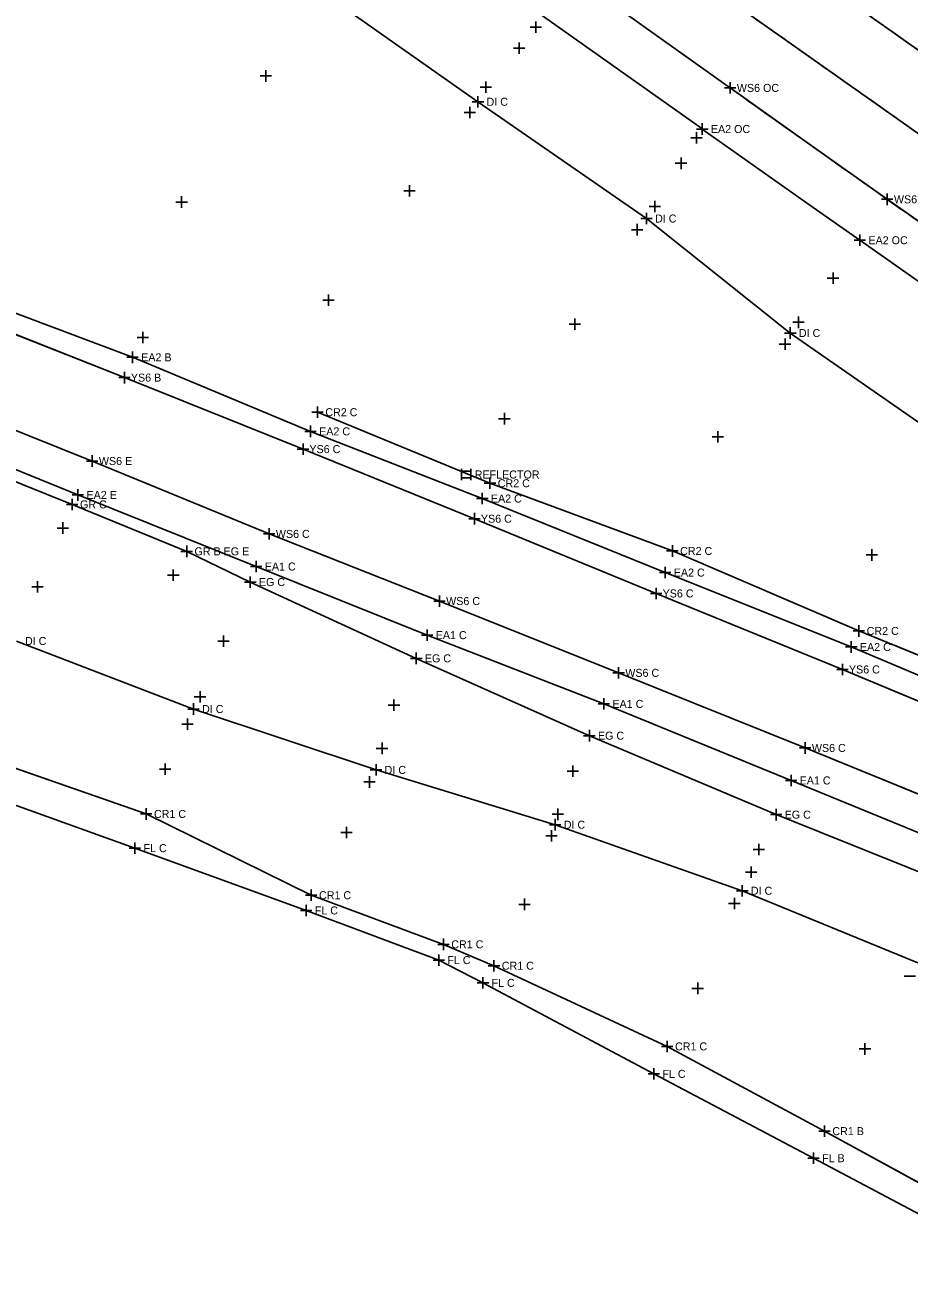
# Model space of a CAD drawing. Extents: x 1324236 to 1326110, y 459090 to 460782.
# Drawn here: x 1325184.1 to 1325338.7, y 459654.1 to 459872.5 of the extents above; entities that cross this region are included whole.
import ezdxf

# ---------------------------------------------------------------- set-up
doc = ezdxf.new("R2010")
doc.units = 0
for name, color, linetype in [('BD_X_Canopy', 7, 'Continuous'), ('DR_X_Ditch', 7, 'Continuous'), ('DR_X_Drive_Pipe', 7, 'Continuous'), ('DT_X_Island', 7, 'Continuous'), ('DT_X_Terrain_Ground_Line', 7, 'Continuous'), ('DV_X_Property_Line', 7, 'Continuous'), ('LT_X_Poles', 7, 'Continuous'), ('PM_X_CL_Double_Solid', 7, 'Continuous'), ('PM_X_Edge_Line', 7, 'Continuous'), ('PM_X_Lane_Line', 7, 'Continuous'), ('PM_X_Parking_Lot_Stall', 7, 'Continuous'), ('PV_X_Shoulder', 7, 'Continuous'), ('RW_X_CL', 7, 'Continuous'), ('RW_X_Esmt_SH', 7, 'Continuous')]:
    doc.layers.add(name, color=color, linetype=linetype)

msp = doc.modelspace()

# ---------------------------------------------------------------- linework, layer by layer
at = {"layer": 'BD_X_Canopy'}
msp.add_lwpolyline([(1325098.23, 460028.13), (1325120.97, 460011.28), (1325148.51, 459991.16), (1325175.71, 459971.23), (1325203.74, 459951.02), (1325230.1, 459931.75), (1325259.75, 459910.43), (1325314.22, 459871.98), (1325314.22, 459871.98), (1325341.7, 459852.6)], dxfattribs=at)
at = {"layer": 'DR_X_Ditch'}
for points in [[(1325105.01, 460038.08), (1325127.7, 460021.23), (1325155.6, 460000.72), (1325182.42, 459981.06), (1325210.57, 459960.69), (1325238.63, 459940.35), (1325308.7, 459890.5), (1325308.7, 459890.5), (1325349.01, 459862.04), (1325349.01, 459862.04), (1325431.77, 459803.91), (1325432.23, 459803.59), (1325432.23, 459803.59), (1325448.95, 459791.99), (1325448.95, 459791.99), (1325460.04, 459784.34), (1325460.04, 459784.34), (1325460.31, 459784.16), (1325460.31, 459784.16), (1325516.92, 459745.67), (1325550.1, 459723.2), (1325550.1, 459723.2), (1325604.67, 459686.51)], [(1325091.37, 460018.48), (1325114.18, 460001.81), (1325140.65, 459982.29), (1325168.98, 459961.47), (1325196.8, 459941.36), (1325224.07, 459921.48), (1325251.92, 459901.3), (1325270.43, 459887.92), (1325270.43, 459887.92), (1325279.78, 459881.23), (1325279.78, 459881.23), (1325307.11, 459861.77), (1325307.43, 459861.54), (1325307.43, 459861.54), (1325324.59, 459849.37), (1325324.59, 459849.37), (1325334.9, 459842.06), (1325334.9, 459842.06), (1325346.76, 459833.74)], [(1325232.73, 459798.38), (1325201.51, 459810.88), (1325169.12, 459823.7), (1325137.45, 459835.9), (1325108.1, 459847.12), (1325079.38, 459859.09), (1325074.32, 459861.12), (1325069.38, 459863.44), (1325069.38, 459863.44), (1325066.03, 459865.32), (1325062.84, 459867.47), (1325062.84, 459867.47), (1325058.04, 459871.12), (1325053.37, 459874.94)], [(1325023.99, 459854.53), (1325029.18, 459854.52), (1325034.35, 459854.01), (1325034.35, 459854.01), (1325045.33, 459852.14), (1325045.33, 459852.14), (1325050.53, 459850.91), (1325050.53, 459850.91), (1325053.41, 459850.06), (1325053.41, 459850.06), (1325072.92, 459844), (1325072.92, 459844), (1325084.48, 459840.09), (1325084.48, 459840.09), (1325102.8, 459833.11), (1325102.8, 459833.11), (1325131.65, 459821.96), (1325163.65, 459809.19), (1325195.86, 459796.3), (1325226.81, 459783.55)], [(1325358.54, 459746.7), (1325327.08, 459759.85), (1325294.49, 459773.14), (1325262.71, 459786.21), (1325232.73, 459798.38)], [(1325351.19, 459733.61), (1325320.55, 459746.12), (1325287.93, 459759.25), (1325256.59, 459771.81), (1325226.81, 459783.55)]]:
    msp.add_lwpolyline(points, dxfattribs=at)
at = {"layer": 'DR_X_Drive_Pipe'}
for p, q in [((1325263.33, 459859.12), (1325236.24, 459878.16)), ((1325292.8, 459838.7), (1325263.33, 459859.12)), ((1325317.95, 459818.68), (1325292.8, 459838.7)), ((1325346.44, 459798.83), (1325317.95, 459818.68)), ((1325213.57, 459752.93), (1325182.61, 459764.82)), ((1325245.5, 459742.28), (1325213.57, 459752.93)), ((1325276.83, 459732.7), (1325245.5, 459742.28)), ((1325309.55, 459721.15), (1325276.83, 459732.7)), ((1325340.23, 459708.56), (1325309.55, 459721.15))]:
    msp.add_line(p, q, dxfattribs=at)
at = {"layer": 'DT_X_Island'}
for p, q in [((1325265.43, 459792.41), (1325235.27, 459804.83)), ((1325297.32, 459780.57), (1325265.43, 459792.41)), ((1325329.94, 459766.58), (1325297.32, 459780.57)), ((1325361.46, 459753.73), (1325329.94, 459766.58)), ((1325205.31, 459734.58), (1325176, 459744.8)), ((1325234.17, 459720.37), (1325205.31, 459734.58)), ((1325257.3, 459711.78), (1325234.17, 459720.37)), ((1325266.13, 459708.04), (1325257.3, 459711.78)), ((1325296.43, 459693.93), (1325266.13, 459708.04)), ((1325323.94, 459679.11), (1325296.43, 459693.93)), ((1325361.32, 459658.63), (1325323.94, 459679.11))]:
    msp.add_line(p, q, dxfattribs=at)
for points in [[(1325361.46, 459753.73), (1325329.94, 459766.58), (1325297.32, 459780.57), (1325265.43, 459792.41), (1325235.27, 459804.83)], [(1325361.32, 459658.63), (1325323.94, 459679.11), (1325296.43, 459693.93), (1325266.13, 459708.04), (1325257.3, 459711.78), (1325234.17, 459720.37), (1325205.31, 459734.58), (1325176, 459744.8), (1325161.88, 459749.12), (1325145.8, 459759.39), (1325115.06, 459766.59), (1325083.29, 459777.3), (1325053.76, 459788.35), (1325045.01, 459789.31), (1325036.49, 459787.96), (1325032.69, 459782.63)], [(1325346.25, 459722.11), (1325315.46, 459734.46), (1325282.81, 459748.27), (1325252.54, 459761.79), (1325223.51, 459775.13), (1325212.39, 459780.5)]]:
    msp.add_lwpolyline(points, dxfattribs=at)
at = {"layer": 'DT_X_Terrain_Ground_Line'}
for p, q in [((1325260.47, 459794.94), (1325260.47, 459792.94)), ((1325260.47, 459794.54), (1325262.06, 459794.54)), ((1325260.47, 459793.34), (1325262.06, 459793.34)), ((1325262.06, 459794.94), (1325262.06, 459792.94))]:
    msp.add_line(p, q, dxfattribs=at)
at = {"layer": 'DV_X_Property_Line'}
for p, q in [((1325302.56, 459853.35), (1325302.56, 459855.35)), ((1325301.56, 459854.35), (1325303.56, 459854.35)), ((1325329.11, 459834.9), (1325331.11, 459834.9)), ((1325330.11, 459833.9), (1325330.11, 459835.9)), ((1325202.93, 459813.43), (1325202.93, 459815.43)), ((1325201.93, 459814.43), (1325203.93, 459814.43)), ((1325234.05, 459800.48), (1325234.05, 459802.48)), ((1325233.05, 459801.48), (1325235.05, 459801.48)), ((1325193.37, 459789.36), (1325193.37, 459791.36)), ((1325192.37, 459790.36), (1325194.37, 459790.36)), ((1325263.09, 459789.74), (1325265.09, 459789.74)), ((1325264.09, 459788.74), (1325264.09, 459790.74)), ((1325224.54, 459776.85), (1325224.54, 459778.85)), ((1325223.51, 459774.13), (1325223.51, 459776.13)), ((1325223.54, 459777.85), (1325225.54, 459777.85)), ((1325295.07, 459776.79), (1325297.07, 459776.79)), ((1325296.07, 459775.79), (1325296.07, 459777.79)), ((1325222.51, 459775.13), (1325224.51, 459775.13)), ((1325253.44, 459765.85), (1325255.44, 459765.85)), ((1325254.44, 459764.85), (1325254.44, 459766.85)), ((1325252.54, 459760.79), (1325252.54, 459762.79)), ((1325327.62, 459763.78), (1325329.62, 459763.78)), ((1325328.62, 459762.78), (1325328.62, 459764.78)), ((1325251.54, 459761.79), (1325253.54, 459761.79)), ((1325285.34, 459752.82), (1325285.34, 459754.82)), ((1325284.34, 459753.83), (1325286.34, 459753.83)), ((1325281.81, 459748.27), (1325283.81, 459748.27)), ((1325282.81, 459747.27), (1325282.81, 459749.27)), ((1325318.08, 459739.44), (1325318.08, 459741.44)), ((1325317.08, 459740.44), (1325319.08, 459740.44)), ((1325314.46, 459734.46), (1325316.46, 459734.46)), ((1325315.46, 459733.46), (1325315.46, 459735.46))]:
    msp.add_line(p, q, dxfattribs=at)
at = {"layer": 'LT_X_Poles'}
msp.add_lwpolyline([(1325105.01, 460038.08), (1325127.7, 460021.23), (1325155.6, 460000.72), (1325182.42, 459981.06), (1325210.57, 459960.69), (1325238.63, 459940.35), (1325308.7, 459890.5), (1325308.7, 459890.5), (1325349.01, 459862.04), (1325349.01, 459862.04), (1325431.77, 459803.91), (1325432.23, 459803.59), (1325432.23, 459803.59), (1325448.95, 459791.99), (1325448.95, 459791.99), (1325460.04, 459784.34), (1325460.04, 459784.34), (1325460.31, 459784.16), (1325460.31, 459784.16), (1325516.92, 459745.67), (1325550.1, 459723.2), (1325550.1, 459723.2), (1325604.67, 459686.51)], dxfattribs=at)
at = {"layer": 'PM_X_CL_Double_Solid'}
for p, q in [((1325203.34, 459728.6), (1325173.99, 459739.13)), ((1325233.29, 459717.71), (1325203.34, 459728.6)), ((1325256.47, 459709.03), (1325233.29, 459717.71)), ((1325264.2, 459705.04), (1325256.47, 459709.03)), ((1325294.08, 459689.13), (1325264.2, 459705.04)), ((1325322.01, 459674.38), (1325294.08, 459689.13)), ((1325360.24, 459654.13), (1325322.01, 459674.38))]:
    msp.add_line(p, q, dxfattribs=at)
at = {"layer": 'PM_X_Edge_Line'}
for p, q in [((1325279.78, 459881.23), (1325307.11, 459861.77)), ((1325201.51, 459810.88), (1325169.12, 459823.7)), ((1325232.73, 459798.38), (1325201.51, 459810.88)), ((1325163.65, 459809.19), (1325195.86, 459796.3)), ((1325262.71, 459786.21), (1325232.73, 459798.38)), ((1325195.86, 459796.3), (1325226.81, 459783.55)), ((1325294.49, 459773.14), (1325262.71, 459786.21)), ((1325256.59, 459771.81), (1325226.81, 459783.55)), ((1325287.93, 459759.25), (1325256.59, 459771.81)), ((1325327.08, 459759.85), (1325294.49, 459773.14)), ((1325320.55, 459746.12), (1325287.93, 459759.25)), ((1325358.54, 459746.7), (1325327.08, 459759.85)), ((1325351.19, 459733.61), (1325320.55, 459746.12))]:
    msp.add_line(p, q, dxfattribs=at)
for centre, radius, start, end in [((1331446.62, 468542.61), 10608.16, 234.647573, 234.914102), ((1325633.49, 460320.38), 562.89, 234.5621, 234.6022), ((1341812.32, 483088.04), 28493.54, 234.602178, 234.644475), ((1331280.44, 468243.86), 10292.71, 234.644475, 234.71485), ((1326291.11, 461193.3), 1655.36, 234.71485, 235.21601)]:
    msp.add_arc(centre, radius, start, end, dxfattribs=at)
at = {"layer": 'PM_X_Lane_Line'}
for centre, radius, start, end in [((1401057.98, 567206.75), 131369.22, 234.7611532, 234.7902308), ((1344588.79, 487185.54), 33429.63, 234.790231, 234.847873)]:
    msp.add_arc(centre, radius, start, end, dxfattribs=at)
at = {"layer": 'PM_X_Parking_Lot_Stall'}
for p, q in [((1325192.37, 459788.71), (1325159.73, 459801.72)), ((1325212.39, 459780.5), (1325192.37, 459788.71))]:
    msp.add_line(p, q, dxfattribs=at)
at = {"layer": 'PV_X_Shoulder'}
for points in [[(1325085.59, 460011.5), (1325108.39, 459994.82), (1325135.87, 459974.49), (1325163.8, 459954.12), (1325191.38, 459934.09), (1325219.2, 459913.96), (1325246.97, 459893.83), (1325265.48, 459880.63), (1325265.48, 459880.63), (1325274.76, 459874.04), (1325274.76, 459874.04), (1325302.45, 459854.43), (1325302.56, 459854.35), (1325302.56, 459854.35), (1325321.38, 459841.06), (1325321.38, 459841.06), (1325330.11, 459834.9), (1325330.11, 459834.9), (1325344.04, 459825.11)], [(1325234.05, 459801.48), (1325202.93, 459814.43), (1325170.18, 459826.73), (1325138.85, 459838.46), (1325108.97, 459849.32), (1325064.65, 459869.16), (1325061.08, 459871.96), (1325057.84, 459875.14), (1325054.97, 459878.66), (1325052.52, 459882.48), (1325052.52, 459882.48), (1325050.29, 459887.07), (1325048.66, 459891.9), (1325047.65, 459896.9), (1325047.65, 459896.9), (1325048.1, 459908.06), (1325059.67, 459926.39), (1325068.28, 459937.87)], [(1325022.6, 459849.51), (1325028.21, 459850.26), (1325033.85, 459850.73), (1325033.85, 459850.73), (1325036.96, 459850.67), (1325040.02, 459850.16), (1325040.02, 459850.16), (1325044.62, 459848.79), (1325049.06, 459846.99), (1325049.06, 459846.99), (1325070.63, 459838.89), (1325100.31, 459827.64), (1325129.15, 459816.15), (1325160.37, 459803.77), (1325193.37, 459790.36), (1325224.54, 459777.85)], [(1325359.98, 459750.59), (1325328.62, 459763.78), (1325296.07, 459776.79), (1325264.09, 459789.74), (1325234.05, 459801.48)], [(1325348.8, 459727.83), (1325318.08, 459740.44), (1325285.34, 459753.83), (1325254.44, 459765.85), (1325224.54, 459777.85)]]:
    msp.add_lwpolyline(points, dxfattribs=at)
at = {"layer": 'RW_X_CL'}
for p, q in [((1325272.43, 459872.15), (1325274.43, 459872.15)), ((1325273.43, 459871.15), (1325273.43, 459873.15)), ((1325269.52, 459868.49), (1325271.52, 459868.49)), ((1325270.52, 459867.49), (1325270.52, 459869.49)), ((1325225.23, 459863.63), (1325227.23, 459863.63)), ((1325226.23, 459862.63), (1325226.23, 459864.63)), ((1325263.69, 459861.66), (1325265.69, 459861.66)), ((1325264.69, 459860.66), (1325264.69, 459862.66)), ((1325306.43, 459861.54), (1325308.43, 459861.54)), ((1325307.43, 459860.54), (1325307.43, 459862.54)), ((1325260.9, 459857.23), (1325262.9, 459857.23)), ((1325261.9, 459856.23), (1325261.9, 459858.23)), ((1325300.56, 459852.82), (1325302.56, 459852.82)), ((1325301.56, 459851.82), (1325301.56, 459853.82)), ((1325297.84, 459848.36), (1325299.84, 459848.36)), ((1325298.84, 459847.36), (1325298.84, 459849.36)), ((1325250.34, 459843.54), (1325252.34, 459843.54)), ((1325251.34, 459842.54), (1325251.34, 459844.54)), ((1325210.51, 459841.59), (1325212.51, 459841.59)), ((1325211.51, 459840.59), (1325211.51, 459842.59)), ((1325294.27, 459839.81), (1325294.27, 459841.81)), ((1325333.9, 459842.06), (1325335.9, 459842.06)), ((1325334.9, 459841.06), (1325334.9, 459843.06)), ((1325293.27, 459840.81), (1325295.27, 459840.81)), ((1325291.17, 459835.75), (1325291.17, 459837.75)), ((1325290.17, 459836.75), (1325292.17, 459836.75)), ((1325324.42, 459828.28), (1325326.42, 459828.28)), ((1325325.42, 459827.28), (1325325.42, 459829.28)), ((1325236.18, 459824.41), (1325238.18, 459824.41)), ((1325237.18, 459823.41), (1325237.18, 459825.41)), ((1325279.27, 459820.22), (1325281.27, 459820.22)), ((1325280.27, 459819.22), (1325280.27, 459821.22)), ((1325318.4, 459820.55), (1325320.4, 459820.55)), ((1325319.4, 459819.55), (1325319.4, 459821.55)), ((1325203.7, 459817.91), (1325205.7, 459817.91)), ((1325204.7, 459816.91), (1325204.7, 459818.91)), ((1325317.02, 459815.74), (1325317.02, 459817.74)), ((1325316.02, 459816.74), (1325318.02, 459816.74)), ((1325200.51, 459810.88), (1325202.51, 459810.88)), ((1325201.51, 459809.88), (1325201.51, 459811.88)), ((1325234.27, 459804.83), (1325236.27, 459804.83)), ((1325235.27, 459803.83), (1325235.27, 459805.83)), ((1325267.94, 459802.7), (1325267.94, 459804.7)), ((1325266.94, 459803.7), (1325268.94, 459803.7)), ((1325304.29, 459800.51), (1325306.29, 459800.51)), ((1325305.29, 459799.51), (1325305.29, 459801.51)), ((1325231.73, 459798.38), (1325233.73, 459798.38)), ((1325232.73, 459797.38), (1325232.73, 459799.38)), ((1325194.86, 459796.3), (1325196.86, 459796.3)), ((1325195.86, 459795.3), (1325195.86, 459797.3)), ((1325265.43, 459791.41), (1325265.43, 459793.41)), ((1325264.43, 459792.41), (1325266.43, 459792.41)), ((1325262.71, 459785.21), (1325262.71, 459787.21)), ((1325189.74, 459784.58), (1325191.74, 459784.58)), ((1325190.74, 459783.58), (1325190.74, 459785.58)), ((1325226.81, 459782.55), (1325226.81, 459784.55)), ((1325261.71, 459786.21), (1325263.71, 459786.21)), ((1325225.81, 459783.55), (1325227.81, 459783.55)), ((1325296.32, 459780.57), (1325298.32, 459780.57)), ((1325297.32, 459779.57), (1325297.32, 459781.57)), ((1325332.21, 459778.87), (1325332.21, 459780.87)), ((1325331.21, 459779.87), (1325333.21, 459779.87)), ((1325209.05, 459776.35), (1325211.05, 459776.35)), ((1325210.05, 459775.35), (1325210.05, 459777.35)), ((1325185.28, 459774.29), (1325187.28, 459774.29)), ((1325186.28, 459773.29), (1325186.28, 459775.29)), ((1325294.49, 459772.14), (1325294.49, 459774.14)), ((1325255.59, 459771.81), (1325257.59, 459771.81)), ((1325256.59, 459770.81), (1325256.59, 459772.81)), ((1325293.49, 459773.14), (1325295.49, 459773.14)), ((1325329.94, 459765.58), (1325329.94, 459767.58)), ((1325218.84, 459763.79), (1325218.84, 459765.79)), ((1325328.94, 459766.58), (1325330.94, 459766.58)), ((1325217.84, 459764.79), (1325219.84, 459764.79)), ((1325327.08, 459758.85), (1325327.08, 459760.85)), ((1325286.93, 459759.25), (1325288.93, 459759.25)), ((1325287.93, 459758.25), (1325287.93, 459760.25)), ((1325326.08, 459759.85), (1325328.08, 459759.85)), ((1325214.72, 459754.08), (1325214.72, 459756.08)), ((1325213.72, 459755.08), (1325215.72, 459755.08)), ((1325248.64, 459752.6), (1325248.64, 459754.6)), ((1325247.64, 459753.6), (1325249.64, 459753.6)), ((1325211.52, 459750.29), (1325213.52, 459750.29)), ((1325212.52, 459749.29), (1325212.52, 459751.29)), ((1325245.55, 459746.05), (1325247.55, 459746.05)), ((1325246.55, 459745.05), (1325246.55, 459747.05)), ((1325319.55, 459746.12), (1325321.55, 459746.12)), ((1325320.55, 459745.12), (1325320.55, 459747.12)), ((1325208.63, 459741.43), (1325208.63, 459743.43)), ((1325279.93, 459741.05), (1325279.93, 459743.05)), ((1325207.63, 459742.43), (1325209.63, 459742.43)), ((1325244.36, 459739.17), (1325244.36, 459741.17)), ((1325278.93, 459742.05), (1325280.93, 459742.05)), ((1325243.36, 459740.17), (1325245.36, 459740.17)), ((1325204.31, 459734.58), (1325206.31, 459734.58)), ((1325205.31, 459733.58), (1325205.31, 459735.58)), ((1325276.29, 459734.52), (1325278.29, 459734.52)), ((1325277.29, 459733.52), (1325277.29, 459735.52)), ((1325240.32, 459730.32), (1325240.32, 459732.32)), ((1325239.32, 459731.32), (1325241.32, 459731.32)), ((1325275.19, 459730.74), (1325277.19, 459730.74)), ((1325276.19, 459729.74), (1325276.19, 459731.74)), ((1325311.45, 459728.35), (1325313.45, 459728.35)), ((1325312.45, 459727.35), (1325312.45, 459729.35)), ((1325310.1, 459724.41), (1325312.1, 459724.41)), ((1325311.1, 459723.41), (1325311.1, 459725.41)), ((1325234.17, 459719.37), (1325234.17, 459721.37)), ((1325233.17, 459720.37), (1325235.17, 459720.37)), ((1325271.45, 459717.78), (1325271.45, 459719.78)), ((1325308.16, 459717.92), (1325308.16, 459719.92)), ((1325270.45, 459718.77), (1325272.45, 459718.77)), ((1325307.16, 459718.92), (1325309.16, 459718.92)), ((1325257.3, 459710.78), (1325257.3, 459712.78)), ((1325256.3, 459711.78), (1325258.3, 459711.78)), ((1325265.13, 459708.04), (1325267.13, 459708.04)), ((1325266.13, 459707.04), (1325266.13, 459709.04)), ((1325337.85, 459706.19), (1325339.85, 459706.19)), ((1325300.75, 459704.08), (1325302.75, 459704.08)), ((1325301.75, 459703.08), (1325301.75, 459705.08)), ((1325296.43, 459692.93), (1325296.43, 459694.93)), ((1325295.43, 459693.93), (1325297.43, 459693.93)), ((1325330.01, 459693.48), (1325332.01, 459693.48)), ((1325331.01, 459692.48), (1325331.01, 459694.48)), ((1325323.94, 459678.11), (1325323.94, 459680.11)), ((1325322.94, 459679.11), (1325324.94, 459679.11))]:
    msp.add_line(p, q, dxfattribs=at)
at = {"layer": 'RW_X_Esmt_SH'}
for p, q in [((1325262.33, 459859.12), (1325264.33, 459859.12)), ((1325263.33, 459858.12), (1325263.33, 459860.12)), ((1325292.8, 459837.7), (1325292.8, 459839.7)), ((1325291.8, 459838.7), (1325293.8, 459838.7)), ((1325317.95, 459817.68), (1325317.95, 459819.68)), ((1325316.95, 459818.68), (1325318.95, 459818.68)), ((1325192.37, 459787.71), (1325192.37, 459789.71)), ((1325191.37, 459788.71), (1325193.37, 459788.71)), ((1325211.39, 459780.5), (1325213.39, 459780.5)), ((1325212.39, 459779.5), (1325212.39, 459781.5)), ((1325213.57, 459751.93), (1325213.57, 459753.93)), ((1325212.57, 459752.93), (1325214.57, 459752.93)), ((1325245.5, 459741.28), (1325245.5, 459743.28)), ((1325244.5, 459742.28), (1325246.5, 459742.28)), ((1325275.83, 459732.7), (1325277.83, 459732.7)), ((1325276.83, 459731.7), (1325276.83, 459733.7)), ((1325202.34, 459728.6), (1325204.34, 459728.6)), ((1325203.34, 459727.6), (1325203.34, 459729.6)), ((1325308.55, 459721.15), (1325310.55, 459721.15)), ((1325309.55, 459720.15), (1325309.55, 459722.15)), ((1325232.29, 459717.71), (1325234.29, 459717.71)), ((1325233.29, 459716.71), (1325233.29, 459718.71)), ((1325255.47, 459709.03), (1325257.47, 459709.03)), ((1325256.47, 459708.03), (1325256.47, 459710.03)), ((1325264.2, 459704.04), (1325264.2, 459706.04)), ((1325263.2, 459705.04), (1325265.2, 459705.04)), ((1325293.08, 459689.13), (1325295.08, 459689.13)), ((1325294.08, 459688.13), (1325294.08, 459690.13)), ((1325322.01, 459673.38), (1325322.01, 459675.38)), ((1325321.01, 459674.38), (1325323.01, 459674.38))]:
    msp.add_line(p, q, dxfattribs=at)

# ---------------------------------------------------------------- texts
at = {"layer": 'DV_X_Property_Line'}
for s, p in [('EA2 OC', (1325304.06, 459853.65)), ('EA2 OC', (1325331.61, 459834.2)), ('EA2 B', (1325204.43, 459813.73)), ('EA2 C', (1325235.55, 459800.78)), ('EA2 E', (1325194.87, 459789.66)), ('EA2 C', (1325265.59, 459789.04)), ('EA1 C', (1325226.04, 459777.15)), ('EG C', (1325225.01, 459774.43)), ('EA2 C', (1325297.57, 459776.09)), ('EA1 C', (1325255.94, 459765.15)), ('EA2 C', (1325330.12, 459763.08)), ('EG C', (1325254.04, 459761.09)), ('EA1 C', (1325286.84, 459753.12)), ('EG C', (1325284.31, 459747.57)), ('EA1 C', (1325319.58, 459739.74)), ('EG C', (1325316.96, 459733.76))]:
    msp.add_text(s, height=1.4, dxfattribs=at).set_placement(p)
at = {"layer": 'RW_X_CL'}
for s, p in [('WS6 OC', (1325308.6, 459860.84)), ('WS6 OC', (1325336.07, 459841.36)), ('YS6 B', (1325202.63, 459810.18)), ('CR2 C', (1325236.63, 459804.13)), ('YS6 C', (1325233.85, 459797.68)), ('WS6 E', (1325197.03, 459795.6)), ('CR2 C', (1325266.79, 459791.71)), ('YS6 C', (1325263.84, 459785.51)), ('WS6 C', (1325227.98, 459782.85)), ('CR2 C', (1325298.68, 459779.87)), ('YS6 C', (1325295.62, 459772.44)), ('WS6 C', (1325257.76, 459771.11)), ('CR2 C', (1325331.3, 459765.88)), ('YS6 C', (1325328.2, 459759.15)), ('WS6 C', (1325289.09, 459758.55)), ('WS6 C', (1325321.72, 459745.42)), ('CR1 C', (1325206.66, 459733.88)), ('CR1 C', (1325235.53, 459719.67)), ('CR1 C', (1325258.66, 459711.08)), ('CR1 C', (1325267.49, 459707.34)), ('CR1 C', (1325297.79, 459693.23)), ('CR1 B', (1325325.3, 459678.41))]:
    msp.add_text(s, height=1.4, dxfattribs=at).set_placement(p)
at = {"layer": 'RW_X_Esmt_SH'}
for s, p in [('DI C', (1325264.83, 459858.42)), ('DI C', (1325294.3, 459838)), ('DI C', (1325319.45, 459817.98)), ('REFLECTOR', (1325262.76, 459793.24)), ('GR C', (1325193.73, 459788.01)), ('GR B EG E', (1325213.75, 459779.8)), ('DI C', (1325184.11, 459764.12)), ('DI C', (1325215.07, 459752.23)), ('DI C', (1325247, 459741.58)), ('DI C', (1325278.33, 459732)), ('FL C', (1325204.84, 459727.9)), ('DI C', (1325311.05, 459720.45)), ('FL C', (1325234.79, 459717.01)), ('FL C', (1325257.97, 459708.33)), ('FL C', (1325265.7, 459704.34)), ('FL C', (1325295.58, 459688.43)), ('FL B', (1325323.51, 459673.68))]:
    msp.add_text(s, height=1.4, dxfattribs=at).set_placement(p)

doc.saveas('drawing.dxf')
